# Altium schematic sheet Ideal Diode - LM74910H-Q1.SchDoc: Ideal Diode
size 431 x 279 mm; Date: Not shown in title block; ApprovedBy: Not shown in title block; CheckedBy: Not shown in title block; Author: Not shown in title block; CompanyName: Not shown in title block; DrawnBy: Hely Zhang; Engineer: Hely Zhang; Organization: Not shown in title block; Address1: Not shown in title block; Address2: Not shown in title block; Address3: Not shown in title block; Address4: Not shown in title block; DocumentNumber: 1; Revision: Use project parameter SCH_Rev; SheetNumber: 3; SheetTotal: 14; PageSetup: Record=PageOptions¦CenterHorizontal=True¦CenterVertical=True¦PrintScale=0.62¦XCorrection=1.00¦YCorrection=1.00¦PrintKind=0¦BorderSize=5000000¦LeftOffset=0¦BottomOffset=0¦Orientation=2¦PaperLength=1000¦PaperWidth=1000¦Scale=100¦PaperSource=15¦PrintQuality=600¦MediaType=1¦DitherType=10¦PrintScaleMode=1¦PaperKind=Letter
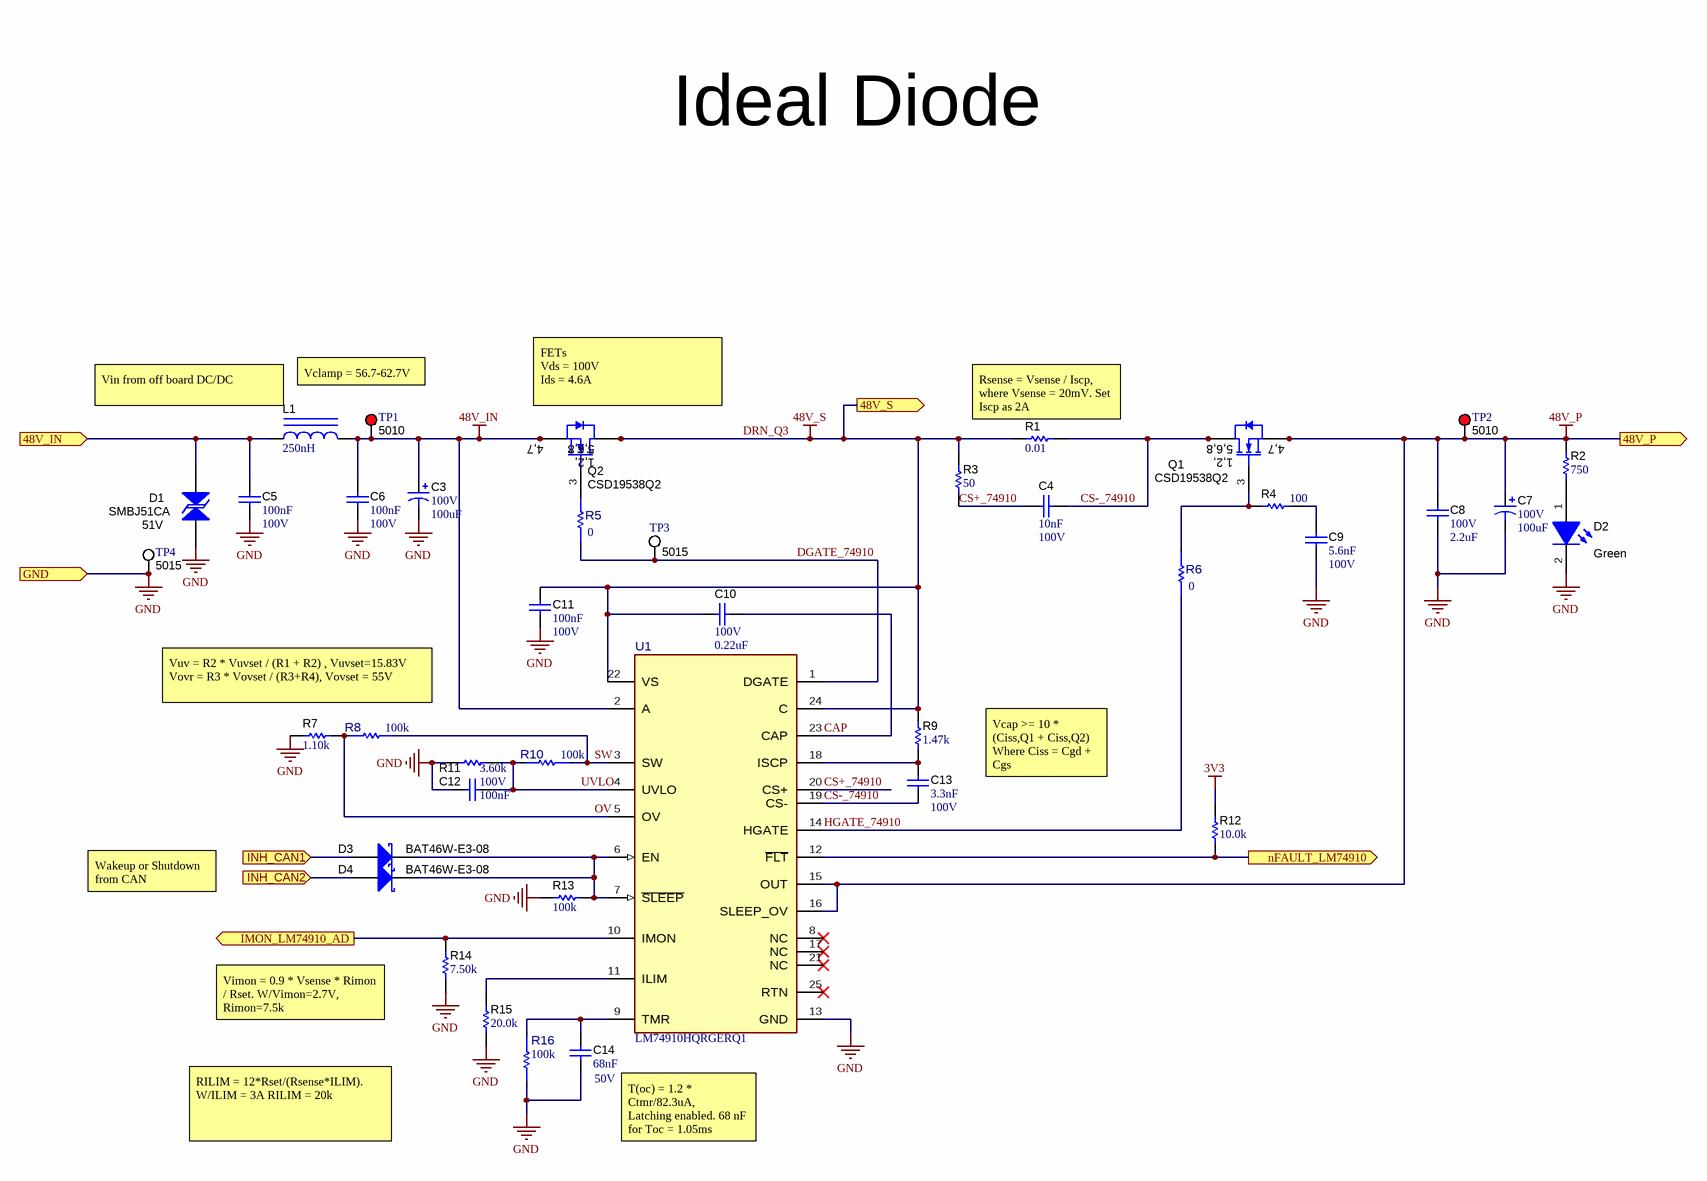
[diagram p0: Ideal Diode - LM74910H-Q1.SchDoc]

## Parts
C3  VDC_V: 100V  ValueDisplayed: 100uF  [SM_RADIAL_J16]  (hidden comment: EEV-FK2A101M)
C4  Cap_F: 10nF  VDC_V: 100V  [0603]  (hidden comment: GRM188R72A103KA01D)
C5  Cap_F: 100nF  VDC_V: 100V  [0603]  (hidden comment: HMK107B7104KAHT)
C6  Cap_F: 100nF  VDC_V: 100V  [0603]  (hidden comment: HMK107B7104KAHT)
C7  VDC_V: 100V  ValueDisplayed: 100uF  [SM_RADIAL_J16]  (hidden comment: EEV-FK2A101M)
C8  VDC_V: 100V  ValueDisplayed: 2.2uF  [1210_270]  (hidden comment: GRM32ER72A225KA35L)
C9  Cap_F: 5.6nF  VDC_V: 100V  [0603]  (hidden comment: GRM188R72A562KA01D)
C10  VDC_V: 100V  ValueDisplayed: 0.22uF  [1206]  (hidden comment: GRM31MR72A224KA01L)
C11  Cap_F: 100nF  VDC_V: 100V  [0603]  (hidden comment: HMK107B7104KAHT)
C12  Cap_F: 100nF  VDC_V: 100V  [0603]  (hidden comment: HMK107B7104KAHT)
C13  Cap_F: 3.3nF  VDC_V: 100V  [0603]  (hidden comment: GCM188R72A332KA37D)
C14  Cap_F: 68nF  VDC_V: 50V  [0603]  (hidden comment: 06035C104KAZ2A)
D1  SMBJ51CA  value 51V  [SMB-Bi]
D2  value Green  [LTST-C191_Green]  (hidden comment: LTST-C191KGKT)
D3  BAT46W-E3-08  [SOD-123]
D4  BAT46W-E3-08  [SOD-123]
L1  ValueDisplayed: 250nH  [WE-HCM_1390]  (hidden comment: 744309025)
Q1  CSD19538Q2  [DQK0006C]
Q2  CSD19538Q2  [DQK0006C]
R1  ValueDisplayed: 0.01  [WSL0603]  (hidden comment: WSL0603R0100FEA)
R2  ValueDisplayed: 750  [0603]  (hidden comment: RC0603FR-07750RL)
R3  ValueDisplayed: 50  [0603]  (hidden comment: CRCW060350R0FKEA)
R4  ValueDisplayed: 100  [0603]  (hidden comment: ERJ-3GEY0R00V)
R5  Res_ohm: 0  [FP-RC0603FR-100RL_0603-MFG]  (hidden comment: RC0603FR-100RL)
R6  Res_ohm: 0  [FP-RC0603FR-100RL_0603-MFG]  (hidden comment: RC0603FR-100RL)
R7  ValueDisplayed: 1.10k  [0603]  (hidden comment: RC0603FR-071K1L)
R8  value 100k  [FP-ERJ-PB3B1003V_0603-IPC_A]  (hidden comment: ERJ-PB3B1003V)
R9  ValueDisplayed: 1.47k  [0603]  (hidden comment: RC0603FR-071K47L)
R10  value 100k  [FP-ERJ-PB3B1003V_0603-IPC_A]  (hidden comment: ERJ-PB3B1003V)
R11  ValueDisplayed: 3.60k  [0603]  (hidden comment: RC0603FR-073K6L)
R12  ValueDisplayed: 10.0k  [0603]  (hidden comment: ERJ-3EKF1002V)
R13  ValueDisplayed: 100k  [0603]  (hidden comment: RT0603BRD07100KL)
R14  ValueDisplayed: 7.50k  [0603]  (hidden comment: RC0603FR-077K5L)
R15  ValueDisplayed: 20.0k  [0603]  (hidden comment: RC0603FR-0720KL)
R16  value 100k  [FP-ERJ-PB3B1003V_0603-IPC_A]  (hidden comment: ERJ-PB3B1003V)
TP1  5010  [Keystone5010]
TP2  5010  [Keystone5010]
TP3  5015  [Testpoint_Keystone_Miniature]
TP4  5015  [Testpoint_Keystone_Miniature]
U1  LM74910HQRGERQ1  [RGE0024T-MFG]

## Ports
48V_IN (in), 48V_P (out), 48V_S (out), GND (in), IMON_LM74910_AD (out), INH_CAN1 (in), INH_CAN2 (in), nFAULT_LM74910 (out)

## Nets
3V3: R12.2
48V_IN: C3.1(+) C6.1 L1.2 Q2.4(S) Q2.7(S) TP1.1 U1.2(A)
48V_P: C7.1(+) C8.1 Q1.4(S) Q1.7(S) R2.2 TP2.1 U1.15(OUT) U1.16(SLEEP_OV) ; port 48V_P
DRN_Q3: C10.1 C11.1 Q2.1(D) Q2.2(D) Q2.5(D) Q2.6(D) Q2.8(D) R1.1 R3.2 R9.2 U1.22(VS) U1.24(C) ; port 48V_S  [also labelled 48V_S]
GND: C3.2(-) C5.2 C6.2 C7.2(-) C8.2 C9.2 C11.2 C12.1 C14.2 D1.1 D2.2(K) R7.1 R11.1 R13.2 R14.1 R15.1 R16.2 TP4.1 U1.13(GND) ; port GND
48V_IN: C5.1 D1.2 L1.1 ; port 48V_IN  [a separate net that carries the same name]
CAP: C10.2 U1.23(CAP)
CS+_74910: C4.2 R3.1 U1.20(CS+)
CS-_74910: C4.1 C13.2 Q1.1(D) Q1.2(D) Q1.5(D) Q1.6(D) Q1.8(D) R1.2 U1.19(CS-)
DGATE_74910: R5.1 TP3.1 U1.1(DGATE)
HGATE_74910: R6.1 U1.14(HGATE)
IMON_LM74910_AD: R14.2 U1.10(IMON) ; port IMON_LM74910_AD
INH_CAN1: D3.2(A) ; port INH_CAN1
INH_CAN2: D4.2(A) ; port INH_CAN2
nFAULT_LM74910: R12.1 U1.12(~{FLT}) ; port nFAULT_LM74910
OV: R7.2 R8.2 U1.5(OV)
SW: R8.1 R10.1 U1.3(SW)
UVLO: C12.2 R10.2 R11.2 U1.4(UVLO)
NetC9_1: C9.1 R4.2
NetC13_1: C13.1 R9.1 U1.18(ISCP)
NetC14_1: C14.1 R16.1 U1.9(TMR)
NetD2_1: D2.1(A) R2.1
NetD3_1: D3.1(K) D4.1(K) R13.1 U1.6(EN) U1.7(~{SLEEP})
NetQ1_3: Q1.3(G) R4.1 R6.2
NetQ2_3: Q2.3(G) R5.2
NetR15_2: R15.2 U1.11(ILIM)

Not connected (* = marked no-connect by the designer): U1 8(NC)* 17(NC)* 21(NC)* 25(RTN)*

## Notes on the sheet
- Ideal Diode
- (near L1) Vin from off board DC/DC
- Vclamp = 56.7-62.7V
- (near Q2) FETs
  Vds = 100V
  Ids = 4.6A
- (near R1) Rsense = Vsense / Iscp, where Vsense = 20mV. Set Iscp as 2A
- Vuv = R2 * Vuvset / (R1 + R2) , Vuvset=15.83V
  Vovr = R3 * Vovset / (R3+R4), Vovset = 55V
- Vcap >= 10 * (Ciss,Q1 + Ciss,Q2)
  Where Ciss = Cgd + Cgs
- Wakeup or Shutdown from CAN
- Vimon = 0.9 * Vsense * Rimon / Rset. W/Vimon=2.7V, Rimon=7.5k
- RILIM = 12*Rset/(Rsense*ILIM). W/ILIM = 3A RILIM = 20k
- T(oc) = 1.2 * Ctmr/82.3uA,
  Latching enabled. 68 nF for Toc = 1.05ms

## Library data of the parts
C3 C7 = CMP-0011221-1: CAP, AL, 100 uF, 100 V, +/- 20%, 0.17 ohm, AEC-Q200 Grade 2, SMD; Manufacturer: Panasonic; TaMin_C: -55°C; ESR_ohm: 0.17; Polarized: Y; SizeAreaWB_mm2: 399; U/M: EA; Value: 100uF; TaMax_C: 105°C; SizeZ_mm: 16.5; SizeX_mm: 19; SizeY_mm: 17; Cap_Case: J16; SizeArea_mm2: 323; CompType: Capacitor; Cap_F: 100µF; IRMS_A: 793mA; AEC Grade: 2; AEC Category: Q200
C4 = CMP-0007468-3: CAP, CERM, 0.01 uF, 100 V, +/- 10%, X7R, 0603; Manufacturer: MuRata; TaMin_C: -55°C; Polarized: N; SizeAreaWB_mm2: 4.68; Value1: Unknown; U/M: EA; Value: 0.01uF; TaMax_C: 125°C; SizeZ_mm: 1; SizeX_mm: 1.6; SizeY_mm: 0.8; SizeArea_mm2: 1.28; AEC Category: Q200
C5 C6 C11 C12 = CMP-0081011-1: CAP, CERM, 0.1 µF, 100 V,+/- 10%, X7R, AEC-Q200 Grade 1, 0603; Manufacturer: Taiyo Yuden; SizeAreaWB_mm2: 4.68; SizeArea_mm2: 1.28; AEC Qualified: Y; AEC Category: Q200; Value: 0.1uF; TaMax_C: 125°C; SizeZ_mm: 1; Polarized: N; TaMin_C: -55°C; SizeY_mm: 0.8; U/M: EA; SizeX_mm: 1.6; ValueDisplayed: 0.1µF
C8 = CMP-0009232-1: CAP, CERM, 2.2 uF, 100 V, +/- 10%, X7R, 1210; Manufacturer: MuRata; TaMin_C: -55°C; ESR_ohm: 7m; Polarized: N; SizeAreaWB_mm2: 14.7; Value1: 0.007 ohm; U/M: EA; Value: 2.2uF; TaMax_C: 125°C; SizeZ_mm: 2.7; SizeX_mm: 3.2; SizeY_mm: 2.5; Cap_Case: 1210; SizeArea_mm2: 8; Cap_F: 2.2µF; IRMS_A: 4.4A; AEC Category: Q200
C9 = CMP-0007485-2: CAP, CERM, 5600 pF, 100 V, +/- 10%, X7R, 0603; Manufacturer: MuRata; TaMin_C: -55°C; Polarized: N; SizeAreaWB_mm2: 4.68; Value1: Unknown; U/M: EA; Value: 5600pF; TaMax_C: 125°C; SizeZ_mm: 1; SizeX_mm: 1.6; SizeY_mm: 0.8; SizeArea_mm2: 1.28; AEC Category: Q200
C10 = CMP-0009002-2: CAP, CERM, 0.22 uF, 100 V, +/- 10%, X7R, 1206; Manufacturer: MuRata; TaMin_C: -55°C; Polarized: N; SizeAreaWB_mm2: 10.92; Value1: Unknown; U/M: EA; Value: 0.22uF; TaMax_C: 125°C; SizeZ_mm: 1.35; SizeX_mm: 3.2; SizeY_mm: 1.6; SizeArea_mm2: 5.12; Cap_F: 220nF; AEC Category: Q200
C13 = CMP-0007148-3: CAP, CERM, 3300 pF, 100 V, +/- 10%, X7R, AEC-Q200 Grade 1, 0603; Manufacturer: MuRata; TaMin_C: -55°C; Polarized: N; SizeAreaWB_mm2: 4.68; Value1: Unknown; U/M: EA; Value: 3300pF; TaMax_C: 125°C; SizeZ_mm: 1; SizeX_mm: 1.6; SizeY_mm: 0.8; SizeArea_mm2: 1.28; AEC Qualified: Y; AEC Category: Q200
C14 = CMP-0079095-1: CAP, CERM, 0.1 µF, 50 V,+/- 10%, X7R, AEC-Q200 Grade 1, 0603; Manufacturer: AVX; SizeAreaWB_mm2: 4.68; SizeArea_mm2: 1.28; AEC Qualified: Y; AEC Category: Q200; Value: 0.1uF; TaMax_C: 125°C; SizeZ_mm: 1; Polarized: N; TaMin_C: -55°C; SizeY_mm: 0.8; U/M: EA; SizeX_mm: 1.6; ValueDisplayed: 0.1µF
D1 = CMP-0006055-3: Diode, TVS, Bi, 51 V, 82.4 Vc, SMB; Manufacturer: Bourns; AEC Category: Q101; AEC Qualified: N; Vbr_Max: 62.7V; Value1: 600W; Vbr_Min: 56.7V; Vc: 82.4V; Ipp: 7.3A
D2 = CMP-0078478-1: LED, Green, SMD; Manufacturer: Lite-On; Io_A: 30mA; Power_TotalModule: 75mW; Green_Lifecycle: Not Set; Vr_V: 5V; Tjmax_C: 85°C; Green_REACh: Incomplete; Value1: 0.075W; Angle: 130; Ir_A: 10µA; Vf_V: 2V; Type: AlInGaP
D3 D4 = CMP-0080760-2: Diode, Schottky, 100 V, 0.15 A, AEC-Q101, SOD-123; Manufacturer: Vishay-Semiconductor; SizeArea_mm2: 6.545; Io_A: 150mA; Vr_V: 100V; Value: 100V; SizeAreaWB_mm2: 13.095; AEC Qualified: Y; Vf_V: 1V; SizeZ_mm: 1.35; Value1: 0.15A; TJmax_C: 125°C; SizeY_mm: 1.7; SizeX_mm: 3.85; AEC Category: Q101
L1 = CMP-0063911-1: Inductor, Shielded Drum Core, Ferrite, 250 nH, 50 A, 0.000165 ohm, SMD; Manufacturer: Wurth Elektronik; Isat: 81A @ 20% inductance drop; Irms: 50A @ 50C rise; Green_Lifecycle: Active; SizeAreaWB_mm2: 240; DCR_ohm: 165µ; Green_REACh: Passed; Value: 250nH; Imax_A: 50A; SizeZ_mm: 9.5; SizeX_mm: 14; SizeY_mm: 13; SizeArea_mm2: 182; AEC Category: Q200
Q1 Q2 = CMP-0000968-2: MOSFET, N-CH, 100 V, 4.5 A, DQK0006C (WSON-6); Alternate Manufacturer: None; Manufacturer: Texas Instruments; SizeZ_mm: 0.8; ChType: N; VdsMax_V: 100V; SizeX_mm: 2; SizeAreaWB_mm2: 9; Vgs_V: 20V; Value: 100V; SizeArea_mm2: 4; AEC Category: Q101; IdsMax_A: 4.5A; U/M: EA
R1 = CMP-0023344-2: RES, 0.01, 1%, 0.1 W, 0603; Manufacturer: Vishay-Dale; Power_W: 100mW; TempCo: 75 ppm/C; Value_Code: R010; U/M: EA; Value: 0.01; EIA_Code: E96; Res_ohm: 10m; SizeX_mm: 1.52; SizeY_mm: 0.76; SizeZ_mm: 0.584; Value2: 0.1W; SizeArea_mm2: 1.1552; AEC Qualified: N; AEC Category: Q200
R2 = CMP-0023266-5: RES, 750, 1%, 0.1 W, 0603; Manufacturer: Yageo; Power_W: 100mW; TempCo: 100 ppm/C; Value_Code: 750R; Value: 750; EIA_Code: E96; SizeX_mm: 1.6; SizeY_mm: 0.8; SizeZ_mm: 1; Value2: 0.1W; SizeArea_mm2: 1.28; AEC Qualified: N; VDC_V: 75V; AEC Category: Q200; SizeAreaWB_mm2: 4.68
R3 = CMP-0022479-4: RES, 50, 1%, 0.1 W, AEC-Q200 Grade 0, 0603; Manufacturer: Vishay-Dale; Power_W: 100mW; TempCo: 100 ppm/C; Value_Code: 50R0; Value: 50; SizeX_mm: 1.6; SizeY_mm: 0.8; SizeZ_mm: 1; Value2: 0.1W; SizeArea_mm2: 1.28; AEC Qualified: Y; VDC_V: 75V; AEC Category: Q200; AEC Grade: 0
R4 = CMP-0025874-4: RES, 0, 5%, 0.1 W, AEC-Q200 Grade 0, 0603; Manufacturer: Panasonic; Power_W: 100mW; TempCo: 600 ppm/C; Value_Code: 0000; Value: 0; EIA_Code: E24; SizeX_mm: 1.6; SizeY_mm: 0.8; SizeZ_mm: 1; Value2: 0.1W; SizeArea_mm2: 1.28; AEC Qualified: Y; VDC_V: 50V; AEC Category: Q200; SizeAreaWB_mm2: 4.68
R5 R6 = CMP-0123755-1: 0 Ohms Jumper Chip Resistor 0603 (1608 Metric) Moisture Resistant Thick Film; Manufacturer: Yageo; AEC Qualified: No; SizeZ_mm: 0.55mm; Tolerance_%: 1%; Value: 0
R7 = CMP-0022870-5: RES, 1.10 k, 1%, 0.1 W, 0603; Manufacturer: Yageo; Power_W: 100mW; TempCo: 100 ppm/C; Value_Code: 1k10; Value: 1.10k; EIA_Code: E96; Res_ohm: 1.1k; SizeX_mm: 1.6; SizeY_mm: 0.8; SizeZ_mm: 1; Value2: 0.1W; SizeArea_mm2: 1.28; AEC Qualified: N; VDC_V: 75V; AEC Category: Q200; SizeAreaWB_mm2: 4.68
R8 R10 R16 = CMP-0092407-1: Res Thick Film 0603 100K Ohm 0.1% 0.2W(1/5W) ±50ppm/°C Pad SMD Automotive T/R; Manufacturer: Panasonic; Power_W: 200mW; VDC_V: 150V; AEC Qualified: Yes; SizeZ_mm: 0.55mm; AEC Grade: Grade 0
R9 = CMP-0022879-5: RES, 1.47 k, 1%, 0.1 W, 0603; Manufacturer: Yageo; Power_W: 100mW; TempCo: 100 ppm/C; Value_Code: 1k47; Value: 1.47k; EIA_Code: E96; SizeX_mm: 1.6; SizeY_mm: 0.8; SizeZ_mm: 1; Value2: 0.1W; SizeArea_mm2: 1.28; AEC Qualified: N; VDC_V: 75V; AEC Category: Q200; SizeAreaWB_mm2: 4.68
R11 = CMP-0023086-5: RES, 3.60 k, 1%, 0.1 W, 0603; Manufacturer: Yageo; Power_W: 100mW; TempCo: 100 ppm/C; Value_Code: 3k60; Value: 3.60k; Res_ohm: 3.6k; SizeX_mm: 1.6; SizeY_mm: 0.8; SizeZ_mm: 1; Value2: 0.1W; SizeArea_mm2: 1.28; AEC Qualified: N; VDC_V: 75V; AEC Category: Q200; SizeAreaWB_mm2: 4.68
R12 = CMP-0022684-3: RES, 10.0 k, 1%, 0.1 W, 0603; Manufacturer: Panasonic; Power_W: 100mW; TempCo: 100 ppm/C; Value_Code: 10k0; U/M: EA; Value: 10.0k; EIA_Code: E96; Res_ohm: 10k; SizeX_mm: 1.6; SizeY_mm: 0.8; SizeZ_mm: 1; Value2: 0.1W; SizeArea_mm2: 1.28; VDC_V: 75V; AEC Category: Q200
R13 = CMP-0023630-1: RES, 100 k, 0.1%, 0.1 W, 0603; Manufacturer: Yageo America; Power_W: 100mW; TempCo: 25 ppm/C; U/M: EA; Value: 100k; EIA_Code: E192; SizeX_mm: 1.6; SizeY_mm: 0.8; SizeZ_mm: 1; Value2: 0.1W; SizeArea_mm2: 1.28; VDC_V: 75V; AEC Category: Q200
R14 = CMP-0023279-5: RES, 7.50 k, 1%, 0.1 W, 0603; Manufacturer: Yageo; Power_W: 100mW; TempCo: 100 ppm/C; Value_Code: 7k50; Value: 7.50k; EIA_Code: E96; Res_ohm: 7.5k; SizeX_mm: 1.6; SizeY_mm: 0.8; SizeZ_mm: 1; Value2: 0.1W; SizeArea_mm2: 1.28; AEC Qualified: N; VDC_V: 75V; AEC Category: Q200; SizeAreaWB_mm2: 4.68
R15 = CMP-0022906-5: RES, 20.0 k, 1%, 0.1 W, 0603; Manufacturer: Yageo; Power_W: 100mW; TempCo: 100 ppm/C; Value_Code: 20k0; Value: 20.0k; EIA_Code: E96; Res_ohm: 20k; SizeX_mm: 1.6; SizeY_mm: 0.8; SizeZ_mm: 1; Value2: 0.1W; SizeArea_mm2: 1.28; AEC Qualified: N; VDC_V: 75V; AEC Category: Q200; SizeAreaWB_mm2: 4.68
TP1 TP2 = CMP-0055147-1: Test Point, Multipurpose, Red, TH; Manufacturer: Keystone; CNHeader: FALSE; Green_Lifecycle: Active; Green_REACh: Passed; ContactFinish: Silver; CT: TRUE
TP3 TP4 = CMP-0055152-1: Test Point, Miniature, SMT; Manufacturer: Keystone; CNHeader: FALSE; Green_Lifecycle: Active; Green_REACh: Passed; CT: TRUE
U1 = CMP-0127559-1: Automotive Ideal Diode With Circuit Breaker, Undervoltage, and Overvoltage Protection With Fault Output; Manufacturer: Texas Instruments; SizeZ_mm: 1mm; AEC Qualified: Yes; AEC Grade: Grade 1; Max Supply Voltage: 65V; Min Supply Voltage: 3V; Nominal Supply Current: 675uA; Number Of Outputs: 1; Standoff Height: 0mm; TaMax_C: +125°C; TaMin_C: -40°C; TJmax_C: +150°C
